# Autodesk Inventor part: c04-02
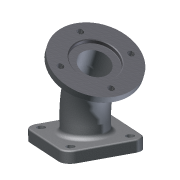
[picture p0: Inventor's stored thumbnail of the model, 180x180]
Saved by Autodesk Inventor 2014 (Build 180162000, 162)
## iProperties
Created: 2010-11
Part Number: c04-02
Material: Generic
Document SubType Name: Modeling
Designer: Thom Tremblay
Density: 1 g/cm^3
Appearance: Aluminum Cast
Author: Thom Tremblay
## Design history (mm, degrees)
sketch "Sketch1"
  geometry: L1 (50, 50)-(50, -50); L2 (50, -50)-(-50, -50); L3 (-50, -50)-(-50, 50); L4 (-50, 50)-(50, 50); C1 r 28 at (0, 0); C2 r 20 at (0, 0); 2 further points
  constraints: 8 end point, 3 coincident, 2 centre point, 1 horizontal, 9 other
  dimensions: "d0" = 100 distance of L3.end L1.start; "d8" = 8 radial gap between concentric circles of C1 C2; "d17" = 40 diameter of C2
extrude "Extrusion1" new body sketch "Sketch1" distance "d1" = 15; taper "d2" = 0 deg
sketch "Sketch2"
  geometry: L1 (0, 0)-(0, 30); L2 (-13.397, 80)-(-28.397, 105.981); A1 r 100 centre (-100, 30) between (0, 30) and (-13.397, 80)
  constraints: 4 end point, 2 point on circle, 2 tangent, 1 centre point, 1 vertical
  dimensions: "d3" = 30 distance of L1.start L1.end; "d4" = 30 distance of L2.start L2.end; "d5" = 150 deg angle of L1 L2; "d6" = 100 radius of A1
workplane "Work Plane1"
sketch "Sketch3"
  geometry: C1 r 55 at (0, 0); 2 further points
  constraints: 1 centre point, 1 coincident
  dimensions: "d9" = 110 diameter of C1
extrude "Extrusion2" join sketch "Sketch3" distance "d10" = 10; taper "d11" = 0 deg
sweep "Sweep1" dims "d12" = 0
sweep "Sweep2" dims "d13" = 0
fillet "Fillet1" dims "d14" = 14, "d15" = 6, "d16" = 2
hole "Hole1" diameter "d20" = 11; stored, may be unused: countersink angle "d24" = 90 deg, drill point angle "d26" = 118 deg; dims "d18" = 10, "d19" = 10, "d21" = 6, "d22" = 20, "d23" = 2, "d25" = 8
hole "Hole2" diameter "d29" = 11; stored, may be unused: countersink angle "d33" = 90 deg, drill point angle "d35" = 118 deg; dims "d27" = 10, "d28" = 10, "d30" = 6, "d31" = 20, "d32" = 2, "d34" = 8
hole "Hole3" diameter "d38" = 11; stored, may be unused: countersink angle "d42" = 90 deg, drill point angle "d44" = 118 deg; dims "d36" = 10, "d37" = 10, "d39" = 6, "d40" = 20, "d41" = 2, "d43" = 8
hole "Hole4" diameter "d47" = 11; stored, may be unused: countersink angle "d51" = 90 deg, drill point angle "d53" = 118 deg; dims "d45" = 10, "d46" = 10, "d48" = 6, "d49" = 20, "d50" = 2, "d52" = 8
sketch "Sketch4" dims "d54" = 85
  geometry: L1 (0, 42.5)-(42.5, 0); L2 (42.5, 0)-(0, -42.5); L3 (0, -42.5)-(-42.5, 0); L4 (-42.5, 0)-(0, 42.5); C1 r 55 at (0, 0) reference; 3 further points
  constraints: 8 end point, 2 coincident, 1 vertical alignment, 11 other
hole "Hole5" sketch "Sketch4" at (0, 42.5), (42.5, 0), (0, -42.5), (-42.5, 0) diameter "d55" = 8.376; stored, may be unused: countersink angle "d59" = 90 deg, drill point angle "d61" = 118 deg; dims "d56" = 6, "d57" = 20, "d58" = 2, "d60" = 8
sketch "Sketch5"
  geometry: C1 r 55 at (0, 0) reference; C2 r 30 at (0, 0); 1 further point
  constraints: 1 centre point, 1 coincident
  dimensions: "d62" = 60 diameter of C2
extrude "Extrusion3" cut sketch "Sketch5" distance "d63" = 6; taper "d64" = 0 deg
sketch "Sketch6"
  geometry: C1 r 20 at (0, 0) reference; C2 r 30 at (0, 0); C3 r 33 at (0, 0)
  constraints: 2 centre point, 1 coincident
  dimensions: "d65" = 60 diameter of C2; "d66" = 3 radial gap between concentric circles of C3 C2
extrude "Extrusion4" cut sketch "Sketch6" distance "d67" = 3; taper "d68" = 0 deg
fillet "Fillet2" dims "d69" = 0.5
chamfer "Chamfer1" distance "d70" = 2; stored, may be unused: second distance "d71" = 2, angle "d72" = 45 deg
chamfer "Chamfer2" distance "d73" = 1; stored, may be unused: second distance "d74" = 2, angle "d75" = 45 deg
fillet "Fillet3" dims "d76" = 0.5
body "Solid1"
